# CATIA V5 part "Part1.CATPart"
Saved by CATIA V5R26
Part number: Part1
Bounding box of the stored display mesh (mm): x 0 to 40, y 0 to 30, z 0 to 30
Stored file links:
  C:\Users\william\Documents\Training\3- How to Traverse Data\3-Prototypes\CV5\Part1.CATPart
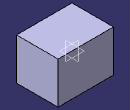
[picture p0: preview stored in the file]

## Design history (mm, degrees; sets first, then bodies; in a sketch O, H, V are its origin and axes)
Body1 (main body)
  Sketch1 on yz-plane, origin (0, 0, 0), H (0, 1, 0), V (0, 0, 1)
    line L1 (0, 0) -> (30, 0)
    line L2 (30, 0) -> (30, 30)
    line L3 (30, 30) -> (0, 30)
    line L4 (0, 30) -> (0, 0)
    horizontal: L1 H, L3 H
    vertical: L2 V, L4 V
  Pad1: profile Sketch1, direction (1, 0, 0), length 40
